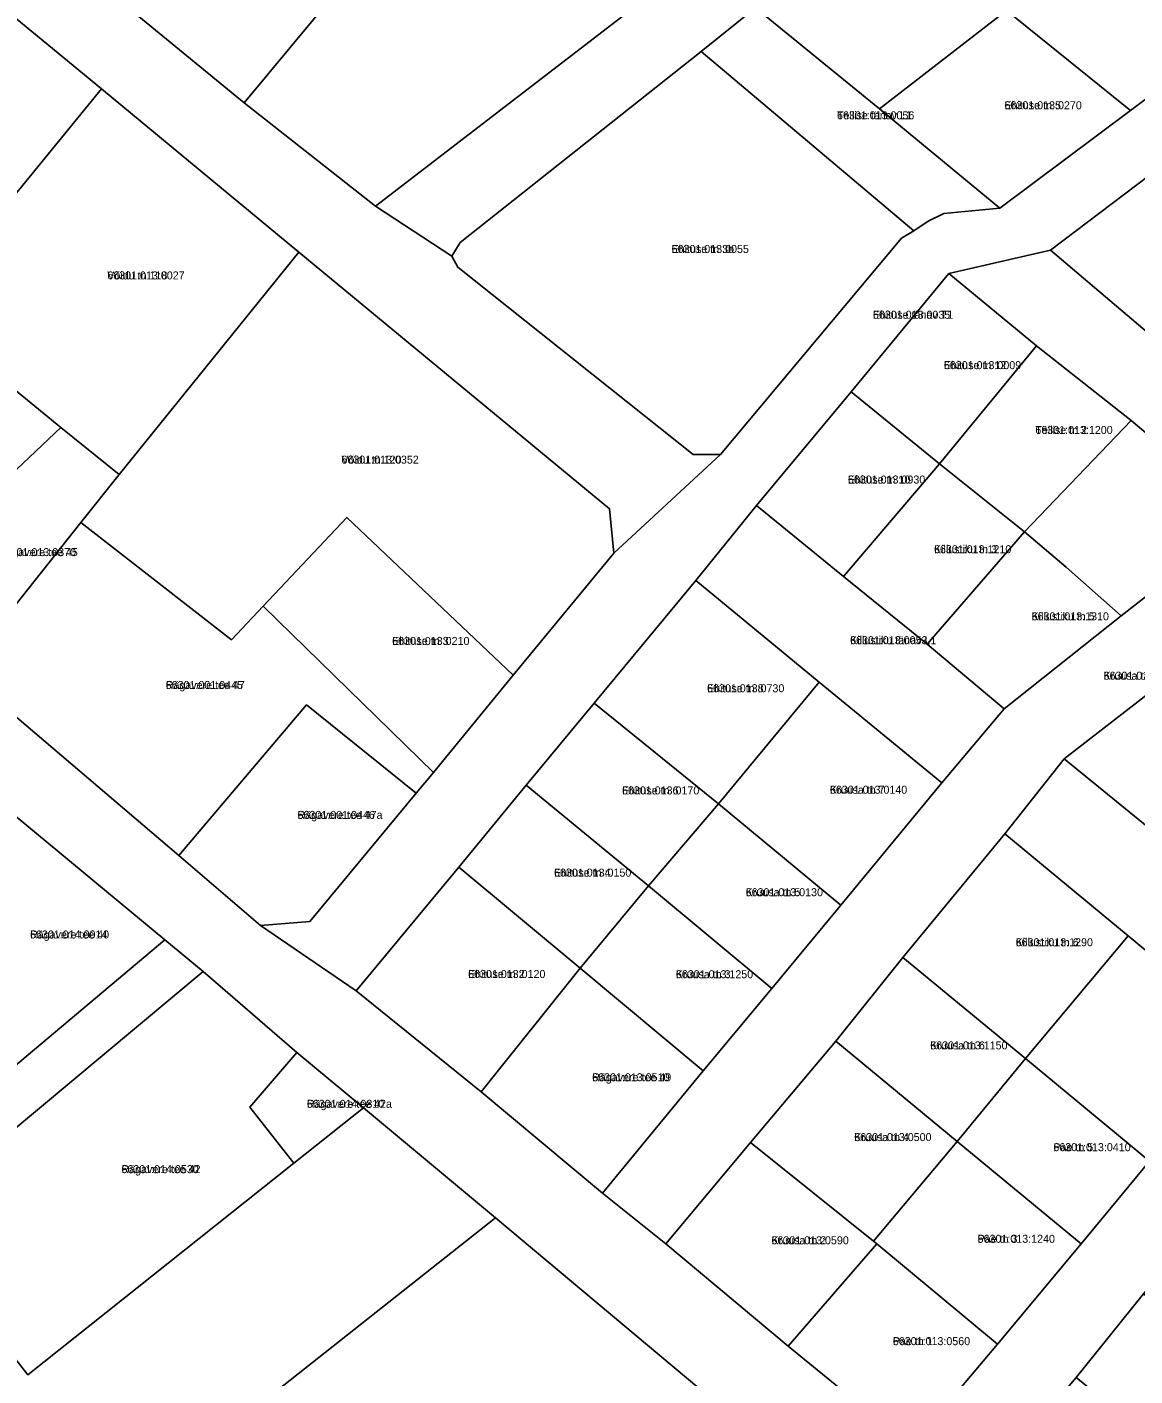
# Model space of a CAD drawing. Extents: x 632278 to 636344, y 6578401 to 6583362.
# Drawn here: x 635426 to 635633.8, y 6580365.1 to 6580618 of the extents above; entities that cross this region are included whole.
import ezdxf

# ---------------------------------------------------------------- set-up
doc = ezdxf.new("R2010")
doc.units = 0
for name, color, linetype in [('L_AADRESS', 7, 'Continuous'), ('PIIR', 7, 'Continuous'), ('TUNNUS', 7, 'Continuous')]:
    doc.layers.add(name, color=color, linetype=linetype)

msp = doc.modelspace()

# ---------------------------------------------------------------- linework, layer by layer
at = {"layer": 'PIIR'}
for points in [[(635491.34, 6580584.37), (635590.03, 6580660.25), (635719.26, 6580759.98), (635723.83, 6580745.48), (635692.65, 6580721.56), (635674.77, 6580707.82), (635658.77, 6580695.56), (635634.87, 6580677.21), (635610.29, 6580658.05), (635587.16, 6580640.44), (635562.6, 6580621.54), (635552.41, 6580613.37), (635507.23, 6580577.53), (635505.71, 6580575)], [(635301.65, 6580728), (635302.22, 6580721.37), (635349.63, 6580691.38), (635385.82, 6580668.52), (635399.52, 6580659.13), (635439.36, 6580626.26), (635466.73, 6580603.71), (635491.34, 6580584.37), (635505.71, 6580575), (635506.83, 6580572.93), (635550.93, 6580537.83), (635556.08, 6580537.84), (635536.04, 6580519.31), (635535.24, 6580527.65), (635476.99, 6580575.76), (635439.96, 6580606.35), (635386.61, 6580650.28), (635366.24, 6580663.41), (635352.32, 6580672.11), (635294.17, 6580708.54), (635287.9, 6580706.65)], [(635452.97, 6580712.75), (635499.83, 6580721.97), (635535.63, 6580712.75), (635556.8, 6580699.92), (635590.03, 6580660.25), (635491.34, 6580584.37), (635466.73, 6580603.71), (635501.25, 6580645.31), (635479.97, 6580675.14)], [(635439.36, 6580626.26), (635479.97, 6580675.14), (635501.25, 6580645.31), (635466.73, 6580603.71)], [(635439.96, 6580606.35), (635405.16, 6580563.82), (635393.54, 6580573.23), (635365.03, 6580538.08), (635345.26, 6580554.6), (635361.9, 6580575.11), (635349.56, 6580585.5), (635333.5, 6580599.08), (635357.86, 6580621.62), (635361.34, 6580625.09), (635386.61, 6580650.28)], [(635562.6, 6580621.54), (635587.16, 6580640.44), (635609.73, 6580621.07), (635585.9, 6580602.63)], [(635633.91, 6580639.12), (635657.14, 6580620.49), (635632.93, 6580602.28), (635609.73, 6580621.07)], [(635562.6, 6580621.54), (635585.9, 6580602.63), (635608.44, 6580584), (635597.93, 6580583), (635594.98, 6580581.56), (635592.32, 6580579.75), (635552.41, 6580613.37)], [(635608.44, 6580584), (635585.9, 6580602.63), (635609.73, 6580621.07), (635632.93, 6580602.28)], [(635552.41, 6580613.37), (635592.32, 6580579.75), (635590.03, 6580578.36), (635556.08, 6580537.84), (635550.93, 6580537.83), (635506.83, 6580572.93), (635505.71, 6580575), (635507.23, 6580577.53)], [(635439.96, 6580606.35), (635476.99, 6580575.76), (635443.3, 6580534.06), (635432.37, 6580542.88), (635416.27, 6580556), (635405.16, 6580563.82)], [(635617.94, 6580576.14), (635636.48, 6580590.11), (635654.53, 6580561.31), (635643.54, 6580554.47)], [(635476.99, 6580575.76), (635535.24, 6580527.65), (635536.04, 6580519.31), (635517.18, 6580496.45), (635486.02, 6580526.02), (635470.31, 6580509.42), (635464.35, 6580503.1), (635436.1, 6580525.05), (635443.3, 6580534.06)], [(635617.94, 6580576.14), (635643.54, 6580554.47), (635648.64, 6580550.15), (635668.82, 6580533.07), (635654.74, 6580525.98), (635633.09, 6580544.17), (635615.32, 6580558.21), (635598.91, 6580571.74)], [(635580.58, 6580549.55), (635598.91, 6580571.74), (635615.32, 6580558.21), (635597.12, 6580536.05)], [(635597.12, 6580536.05), (635615.32, 6580558.21), (635633.09, 6580544.17), (635613.1, 6580523.3)], [(635387.14, 6580519.56), (635416.27, 6580556), (635432.37, 6580542.88), (635398.1, 6580510.53)], [(635580.58, 6580549.55), (635597.12, 6580536.05), (635579.1, 6580514.93), (635562.81, 6580528.26)], [(635620.87, 6580516.71), (635613.1, 6580523.3), (635633.09, 6580544.17), (635654.74, 6580525.98), (635631.21, 6580507.57)], [(635398.1, 6580510.53), (635432.37, 6580542.88), (635443.3, 6580534.06), (635436.1, 6580525.05), (635413.91, 6580497.17)], [(635597.12, 6580536.05), (635613.1, 6580523.3), (635594.79, 6580502.29), (635579.1, 6580514.93)], [(635562.81, 6580528.26), (635579.1, 6580514.93), (635594.79, 6580502.29), (635609.26, 6580490.17), (635597.6, 6580476.27), (635574.57, 6580495.13), (635551.45, 6580514.18)], [(635454.49, 6580462.68), (635413.91, 6580497.17), (635436.1, 6580525.05), (635464.35, 6580503.1), (635470.31, 6580509.42), (635502.24, 6580478.24), (635498.99, 6580474.32), (635478.43, 6580490.9)], [(635502.24, 6580478.24), (635470.31, 6580509.42), (635486.02, 6580526.02), (635517.18, 6580496.45)], [(635594.79, 6580502.29), (635613.1, 6580523.3), (635620.87, 6580516.71), (635631.21, 6580507.57), (635609.26, 6580490.17)], [(635551.45, 6580514.18), (635574.57, 6580495.13), (635555.67, 6580472.34), (635532.36, 6580491.22)], [(635591.82, 6580351.91), (635608.04, 6580371.06), (635623.68, 6580389.87), (635636.52, 6580405.39), (635655.62, 6580428.51), (635667.08, 6580442.68), (635686.71, 6580466.19), (635707.04, 6580490.82), (635708.89, 6580493.06), (635714.06, 6580498.56), (635756.47, 6580515.62), (635764.72, 6580502.67), (635741.92, 6580493.69), (635722.58, 6580485.64), (635699.1, 6580457.17), (635679.06, 6580432.87), (635667.18, 6580418.97), (635648.14, 6580395.77), (635635.42, 6580380.52), (635622.77, 6580364.81), (635603.53, 6580341.98)], [(635645.77, 6580500.31), (635665.2, 6580484.07), (635645.18, 6580460.65), (635620.52, 6580480.76)], [(635574.57, 6580495.13), (635597.6, 6580476.27), (635578.66, 6580453.34), (635555.67, 6580472.34)], [(635469.81, 6580449.57), (635454.49, 6580462.68), (635478.43, 6580490.9), (635498.99, 6580474.32), (635479.04, 6580450.32)], [(635532.36, 6580491.22), (635555.67, 6580472.34), (635542.58, 6580457), (635519.61, 6580475.82)], [(635609.37, 6580466.7), (635620.52, 6580480.76), (635645.18, 6580460.65), (635667.08, 6580442.68), (635655.62, 6580428.51), (635632.49, 6580447.6)], [(635519.61, 6580475.82), (635542.58, 6580457), (635529.73, 6580441.57), (635507.02, 6580460.49)], [(635421.25, 6580472.2), (635451.83, 6580446.86), (635422.32, 6580422.01), (635396.81, 6580452.94)], [(635555.67, 6580472.34), (635578.66, 6580453.34), (635565.69, 6580437.72), (635542.58, 6580457)], [(635609.37, 6580466.7), (635632.49, 6580447.6), (635613.29, 6580424.6), (635590.24, 6580443.56)], [(635511.19, 6580418.34), (635487.73, 6580437.31), (635507.02, 6580460.49), (635529.73, 6580441.57)], [(635542.58, 6580457), (635565.69, 6580437.72), (635552.79, 6580422.33), (635529.73, 6580441.57)], [(635451.83, 6580446.86), (635459.02, 6580440.91), (635403.27, 6580394.42), (635393.37, 6580386.15), (635381.24, 6580401.53), (635338.65, 6580366.81), (635351.3, 6580351.27), (635317.1, 6580323.16), (635285.73, 6580362.69), (635309.75, 6580382.35), (635322.94, 6580366.2), (635375.2, 6580408.77), (635406.27, 6580433.76), (635392.98, 6580449.85), (635395.96, 6580452.27), (635396.81, 6580452.94), (635422.32, 6580422.01)], [(635613.29, 6580424.6), (635632.49, 6580447.6), (635655.62, 6580428.51), (635636.52, 6580405.39)], [(635590.24, 6580443.56), (635613.29, 6580424.6), (635600.45, 6580409.07), (635577.67, 6580427.88)], [(635403.27, 6580394.42), (635459.02, 6580440.91), (635476.63, 6580425.76), (635467.81, 6580415.49), (635476.07, 6580404.98), (635426.14, 6580365.34)], [(635529.73, 6580441.57), (635552.79, 6580422.33), (635533.94, 6580399.4), (635511.19, 6580418.34)], [(635584.73, 6580390.38), (635561.68, 6580408.86), (635577.67, 6580427.88), (635600.45, 6580409.07)], [(635467.81, 6580415.49), (635476.63, 6580425.76), (635489.11, 6580415.36), (635476.07, 6580404.98)], [(635623.68, 6580389.87), (635600.45, 6580409.07), (635613.29, 6580424.6), (635636.52, 6580405.39)], [(635489.11, 6580415.36), (635513.87, 6580394.76), (635447.63, 6580342.41), (635450.21, 6580339.12), (635449.99, 6580338.94), (635467.67, 6580316.49), (635381.07, 6580244.67), (635374.64, 6580252.56), (635336.61, 6580299.27), (635317.1, 6580323.16), (635351.3, 6580351.27), (635393.37, 6580386.15), (635403.27, 6580394.42), (635426.14, 6580365.34), (635476.07, 6580404.98)], [(635561.68, 6580408.86), (635584.73, 6580390.38), (635585.37, 6580389.85), (635568.74, 6580370.72), (635545.81, 6580389.88)], [(635584.73, 6580390.38), (635600.45, 6580409.07), (635623.68, 6580389.87), (635608.04, 6580371.06), (635585.37, 6580389.85)], [(635447.63, 6580342.41), (635513.87, 6580394.76), (635592.45, 6580328.94), (635511.73, 6580261.79), (635468.5, 6580316.13)], [(635608.04, 6580371.06), (635591.82, 6580351.91), (635568.74, 6580370.72), (635585.37, 6580389.85)], [(635622.77, 6580364.81), (635635.42, 6580380.52), (635658.3, 6580361.28), (635645.54, 6580346.14), (635638.12, 6580352.4)]]:
    msp.add_lwpolyline(points, close=True, dxfattribs=at)
for points in [[(635636.48, 6580590.11), (635617.94, 6580576.14), (635598.91, 6580571.74), (635580.58, 6580549.55), (635562.81, 6580528.26), (635551.45, 6580514.18), (635532.36, 6580491.22), (635519.61, 6580475.82), (635507.02, 6580460.49), (635487.73, 6580437.31), (635469.81, 6580449.57), (635479.04, 6580450.32), (635498.99, 6580474.32), (635502.24, 6580478.24), (635517.18, 6580496.45), (635536.04, 6580519.31), (635556.08, 6580537.84), (635590.03, 6580578.36), (635592.32, 6580579.75), (635594.98, 6580581.56), (635597.93, 6580583), (635608.44, 6580584), (635632.93, 6580602.28), (635657.14, 6580620.49)], [(635645.77, 6580500.31), (635620.52, 6580480.76), (635609.37, 6580466.7), (635590.24, 6580443.56), (635577.67, 6580427.88), (635561.68, 6580408.86), (635545.81, 6580389.88), (635533.94, 6580399.4), (635552.79, 6580422.33), (635565.69, 6580437.72), (635578.66, 6580453.34), (635597.6, 6580476.27), (635609.26, 6580490.17), (635631.21, 6580507.57), (635654.74, 6580525.98)], [(635413.91, 6580497.17), (635454.49, 6580462.68), (635469.81, 6580449.57), (635487.73, 6580437.31), (635511.19, 6580418.34), (635533.94, 6580399.4), (635545.81, 6580389.88), (635568.74, 6580370.72), (635591.82, 6580351.91), (635603.53, 6580341.98), (635618.76, 6580329.45), (635634.2, 6580316.79), (635649.69, 6580303.82), (635675.14, 6580283.28), (635684.6, 6580275.4), (635692.42, 6580268.95), (635707.7, 6580256.38), (635719.38, 6580246.9), (635734.44, 6580233.83), (635750.34, 6580221.86), (635773.41, 6580202.85)], [(635748.53, 6580191), (635607.93, 6580306.59), (635600.03, 6580313.12), (635592.45, 6580328.94), (635513.87, 6580394.76), (635489.11, 6580415.36), (635476.63, 6580425.76), (635459.02, 6580440.91), (635451.83, 6580446.86), (635421.25, 6580472.2)]]:
    msp.add_lwpolyline(points, dxfattribs=at)

# ---------------------------------------------------------------- texts
at = {"layer": 'L_AADRESS'}
for s, p in [('Tellise tänav L1', (635577.91, 6580600.65)), ('Ehituse tn 5', (635609.32, 6580602.54)), ('Ehituse tn 3b', (635546.89, 6580575.6)), ('Võidu tn 118', (635441.07, 6580570.64)), ('Ehituse tänav T1', (635584.65, 6580563.27)), ('Ehituse tn 12', (635597.95, 6580553.82)), ('Tellise tn 2', (635615.11, 6580541.67)), ('Võidu tn 120', (635484.98, 6580536.11)), ('Ehituse tn 10', (635579.96, 6580532.38)), ('Rägavere tee 45', (635420.7, 6580518.78)), ('Killustiku tn 3', (635596.1, 6580519.32)), ('Killustiku tn 5', (635614.41, 6580506.74)), ('Ehituse tn 3', (635494.48, 6580502.13)), ('Killustiku tänav L1', (635580.37, 6580502.27)), ('Kruusa tänav L1', (635627.91, 6580495.61)), ('Rägavere tee 47', (635452.02, 6580493.87)), ('Ehituse tn 8', (635553.54, 6580493.26)), ('Ehituse tn 6', (635537.59, 6580474.11)), ('Kruusa tn 7', (635576.58, 6580474.24)), ('Rägavere tee 47a', (635476.74, 6580469.52)), ('Ehituse tn 4', (635524.84, 6580458.7)), ('Kruusa tn 5', (635560.78, 6580455.03)), ('Rägavere tee 40', (635426.58, 6580447.11)), ('Killustiku tn 6', (635611.41, 6580445.65)), ('Ehituse tn 2', (635508.73, 6580439.7)), ('Kruusa tn 3', (635547.69, 6580439.66)), ('Kruusa tn 6', (635595.39, 6580426.32)), ('Rägavere tee 49', (635531.99, 6580420.35)), ('Rägavere tee 42a', (635478.5, 6580415.37)), ('Kruusa tn 4', (635581.14, 6580409.13)), ('Pae tn 5', (635618.48, 6580407.24)), ('Rägavere tee 42', (635443.72, 6580403.12)), ('Kruusa tn 2', (635565.62, 6580389.79)), ('Pae tn 3', (635604.28, 6580390.07)), ('Pae tn 1', (635588.38, 6580370.88))]:
    msp.add_text(s, height=1.5, dxfattribs=at).set_placement(p)
at = {"layer": 'TUNNUS'}
for s, p in [('66301:013:0056', (635577.91, 6580600.65)), ('66301:013:0270', (635609.32, 6580602.54)), ('66301:013:0055', (635546.89, 6580575.6)), ('66301:013:0027', (635441.07, 6580570.64)), ('66301:013:0035', (635584.65, 6580563.27)), ('66301:013:0009', (635597.95, 6580553.82)), ('66301:013:1200', (635615.11, 6580541.67)), ('66301:013:0352', (635484.98, 6580536.11)), ('66301:013:0930', (635579.96, 6580532.38)), ('66301:013:0370', (635420.7, 6580518.78)), ('66301:013:1210', (635596.1, 6580519.32)), ('66301:013:1310', (635614.41, 6580506.74)), ('66301:013:0210', (635494.48, 6580502.13)), ('66301:013:0053', (635580.37, 6580502.27)), ('66301:013:0048', (635627.91, 6580495.61)), ('66301:001:0445', (635452.02, 6580493.87)), ('66301:013:0730', (635553.54, 6580493.26)), ('66301:013:0140', (635576.58, 6580474.24)), ('66301:013:0170', (635537.59, 6580474.11)), ('66301:001:0446', (635476.74, 6580469.52)), ('66301:013:0150', (635524.84, 6580458.7)), ('66301:013:0130', (635560.78, 6580455.03)), ('66301:014:0014', (635426.58, 6580447.11)), ('66301:013:1290', (635611.41, 6580445.65)), ('66301:013:0120', (635508.73, 6580439.7)), ('66301:013:1250', (635547.69, 6580439.66)), ('66301:013:1150', (635595.39, 6580426.32)), ('66301:013:0510', (635531.99, 6580420.35)), ('66301:014:0810', (635478.5, 6580415.37)), ('66301:013:0500', (635581.14, 6580409.13)), ('66301:013:0410', (635618.48, 6580407.24)), ('66301:014:0530', (635443.72, 6580403.12)), ('66301:013:0590', (635565.62, 6580389.79)), ('66301:013:1240', (635604.28, 6580390.07)), ('66301:013:0560', (635588.38, 6580370.88))]:
    msp.add_text(s, height=1.5, dxfattribs=at).set_placement(p)

doc.saveas('drawing.dxf')
